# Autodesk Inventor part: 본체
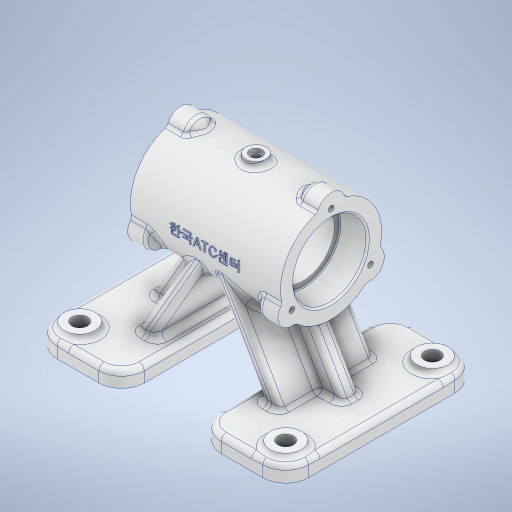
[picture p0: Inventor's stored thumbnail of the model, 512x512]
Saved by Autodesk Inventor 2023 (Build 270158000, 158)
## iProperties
Created: 2026-04
Part Number: 본체
Material: 알루미늄 6061
Document SubType Name: Modeling
Designer: 4강의실
Density: 2.7 g/cm^3
Appearance: 알루미늄 - 평지
Mass: 773.015 g
Surface Area: 685.715 cm^2
Volume: 286.302 cm^3
Author: 4강의실
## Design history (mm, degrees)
sketch "스케치1"
  geometry: L1 (-72, 55)-(72, 55); L2 (72, 55)-(72, -55); L3 (72, -55)-(-72, -55); L4 (-72, -55)-(-72, 55); L5 (-72, 55)-(72, -55); L6 (72, 55)-(-72, -55); L7 (-22, 55)-(22, 55); L8 (22, 55)-(22, -55); L9 (22, -55)-(-22, -55); L10 (-22, -55)-(-22, 55); L11 (-22, 55)-(22, -55); L12 (22, 55)-(-22, -55); 5 further points
  constraints: 24 end point, 4 midpoint, 4 parallel, 2 perpendicular, 1 collinear, 1 horizontal
  dimensions: "d0" = 144 distance of L1.start L1.end; "d1" = 110 distance of L1.end L2.end; "d2" = 44 distance of L7.start L7.end; "d3" = 110 distance of L9.end L7.start; "d116" = 50 distance from line of point (22, 55) L2; "d117" = 0 distance from line of point (22, 55) L1; "d118" = 50 distance from line of point (22, -55) L2; "d119" = 110 distance from line of point (22, -55) L1; "d120" = 94 distance from line of point (-22, 55) L2; "d121" = 0 distance from line of point (-22, 55) L1; "d122" = 94 distance from line of point (-22, -55) L2; "d123" = 110 distance from line of point (-22, -55) L1
extrude "돌출1" new body sketch "스케치1" distance "d4" = 9; taper "d5" = 0 deg
fillet "모깎기1" dims "d6" = 13
sketch "스케치2"
  geometry: L1 (59, -42)-(-59, -42); L2 (-59, -42)-(-59, 42); L3 (-59, 42)-(59, 42); L4 (59, 42)-(59, -42); L5 (59, -42)-(-59, 42); L6 (-59, -42)-(59, 42); C1 r 9 at (-59, 42); C2 r 9 at (-59, -42); C3 r 9 at (59, -42); C4 r 9 at (59, 42); 1 further point
  constraints: 12 end point, 4 centre point, 4 coincident, 2 midpoint, 2 parallel, 1 horizontal, 1 perpendicular
  dimensions: "d7" = 118 distance of L1.start L1.end; "d8" = 84 distance of L1.end L2.end; "d9" = 18 diameter of C1; "d10" = 18 diameter of C2; "d11" = 18 diameter of C3; "d12" = 18 diameter of C4
extrude "돌출2" join sketch "스케치2" distance "d13" = 3; taper "d14" = 0 deg
sketch "스케치3"
  geometry: C1 r 9 at (0, 0) reference; C2 r 9 at (118, 0) reference; C3 r 9 at (118, -84) reference; C4 r 9 at (0, -84) reference; 5 further points
  constraints: 4 coincident
hole "구멍1" sketch "스케치3" at (0, 0), (118, 0), (118, -84), (0, -84) diameter "d15" = 9; stored, may be unused: countersink angle "d19" = 90 deg, drill point angle "d21" = 118 deg; dims "d16" = 12, "d17" = 4, "d18" = 2, "d20" = 14
sketch "스케치4"
  geometry: L1 (0, 0)-(72, 0); C1 r 29 at (72, 0)
  constraints: 2 end point, 1 centre point, 1 coincident, 1 horizontal
  dimensions: "d22" = 72 distance of L1.start L1.end; "d23" = 58 diameter of C1
extrude "돌출3" join sketch "스케치4" stored distance "d24" = 86; taper "d25" = 0 deg
sketch "스케치5"
  geometry: C1 r 29 at (0, 0) reference; 2 further points
  constraints: 1 coincident
hole "구멍2" sketch "스케치5" at (0, 0) diameter "d26" = 36; stored, may be unused: countersink angle "d30" = 90 deg, drill point angle "d32" = 118 deg; dims "d27" = 6, "d28" = 42, "d29" = 16, "d31" = 8
sketch "스케치6"
  geometry: C1 r 18 at (0, 0) reference; C2 r 21 at (0, 0); 1 further point
  constraints: 1 centre point, 1 coincident
  dimensions: "d33" = 42 diameter of C2
extrude "돌출4" cut sketch "스케치6" distance "d34" = 16; taper "d35" = 0 deg
sketch "스케치7" dims "d36" = 52
  geometry: L1 (0, 0)-(0, 26); C1 r 21 at (0, 0) reference; C2 r 8 at (0, 26); 4 further points
  constraints: 2 coincident, 2 end point, 1 centre point, 1 vertical, 3 other
  dimensions: "d38" = 16 diameter of C2
extrude "돌출5" join sketch "스케치7" distance "d39" = 10; taper "d40" = 0 deg
sketch "스케치8"
  geometry: L1 (-33, 99.942)-(-33, 106) reference; L2 (-33, 106)-(-24.181, 97.181); L3 (-33, 101)-(43, 101) reference; L4 (-43, 43)-(43, 43) reference; L5 (27, 90)-(-27, 90) reference; L6 (0, 90)-(0, 112.184); L7 (-33, 106)-(-33, 97.181); L8 (-33, 97.181)-(-24.181, 97.181); L9 (-43, 51)-(-43, 93) reference; L10 (-43, 72)-(0, 72); L11 (-33, 106)-(-33, 98); L12 (-33, 98)-(-20.448, 98); 3 further points
  constraints: 14 end point, 2 midpoint, 2 perpendicular, 2 point on line, 1 horizontal, 1 vertical
  dimensions: "d41" = 45 deg angle of L6 L2; "d42" = 8 distance of L1.end L11.end; "d124" = 7.18091 distance between parallel lines of L5 L8; "d125" = 22.18414 distance from line of L6.end L5; "d126" = 33 distance from line of L10.end L1; "d127" = 12.55187 distance from line of L12.end L1; "d128" = 8 distance from line of point (-25, 98) L5; "d129" = 8 distance from line of point (-25, 98) L1; "d130" = 9.94231 distance from line of point (-33, 99.942) L5; "d131" = 0 distance from line of point (-33, 99.942) L1
revolve "회전1" sketch "스케치8" stored, may be unused: angle "d43" = 90 deg
sketch "스케치9"
  geometry: C1 r 18 at (0, 72) reference; C2 r 21 at (0, 72); 1 further point
  constraints: 1 centre point, 1 coincident
  dimensions: "d47" = 42 diameter of C2
extrude "돌출6" cut sketch "스케치9" distance "d48" = 16; taper "d49" = 0 deg
sketch "스케치10"
  geometry: C1 r 21 at (0, 72) reference; C2 r 21 at (0, 72); 1 further point
  constraints: 1 centre point, 1 coincident
  dimensions: "d50" = 42 diameter of C2
extrude "돌출7" cut sketch "스케치10" distance "d51" = 16; taper "d52" = 0 deg
sketch "스케치11" dims "d53" = 52
  geometry: L1 (0, 72)-(0, 98); C1 r 21 at (0, 72) reference; 3 further points
  constraints: 2 coincident, 2 end point, 1 vertical, 1 vertical alignment, 2 other
hole "구멍3" sketch "스케치11" at (0, 98) diameter "d54" = 3.242; stored, may be unused: countersink angle "d58" = 90 deg, drill point angle "d60" = 118 deg; dims "d55" = 8, "d56" = 42, "d57" = 16, "d59" = 10
sketch "스케치12"
  geometry: L1 (22, 0)-(22, 9) reference; L2 (22, 0)-(32, 0); L3 (35, 0)-(22, 0) reference; L4 (32, 0)-(32, 9); L5 (22, 9)-(35, 9) reference; L6 (32, 9)-(12.37, 43); L7 (-43, 43)-(43, 43) reference; L8 (0, 0)-(0, 43); L9 (19.298, 47)-(41.238, 9); L10 (40, -8)-(22, -8); L11 (35, 9)-(59, 9) reference; L12 (22, 9)-(35, 9) reference; L13 (-43, 43)-(43, 43) reference; L14 (0, 43)-(0, 64.426); L15 (0, 64.426)-(12.37, 43); L16 (0, 64.426)-(0, 80.426); L17 (0, 80.426)-(21.608, 43); 1 further point
  constraints: 20 end point, 8 point on line, 2 vertical, 1 collinear, 1 parallel, 1 perpendicular
  dimensions: "d64" = 10 distance of L1.start L2.end; "d65" = 30 deg angle of L8 L6; "d66" = 8 distance between parallel lines of L6 L9; "d132" = 17 distance between parallel lines of L10 L11; "d133" = 18 distance from line of L10.start L1; "d134" = 0 distance from line of L10.end L1; "d135" = 38 distance from line of L9.start L11; "d136" = 38 distance from line of point (19.298, 47) L11; "d137" = 2.70171 distance from line of point (19.298, 47) L1; "d138" = 34 distance from line of L8.end L11
extrude "돌출8" join sketch "스케치12" stored distance "d67" = 54; taper "d68" = 0 deg
sketch "스케치13"
  geometry: L1 (10.975, 61.417)-(41.238, 9) reference; L2 (35.464, 43)-(55.094, 9); L3 (59, 9)-(35, 9) reference; L4 (-43, 43)-(43, 43) reference; 1 further point
  constraints: 2 end point, 2 point on line, 1 parallel
  dimensions: "d69" = 12 distance between parallel lines of L1 L2
feature "리브1" sketch "스케치13" dims "d70" = 1, "d71" = 10, "d72" = 0, "d73" = 0, "d74" = 1, "d75" = 1
fillet "모깎기2" dims "d76" = 3
fillet "모깎기3" dims "d77" = 3
fillet "모깎기4" dims "d78" = 3
fillet "모깎기6" dims "d80" = 3
fillet "모깎기7" dims "d81" = 3
node "작업 평면1"
sketch "스케치17"
  geometry: C1 r 6 at (0, 0); 1 further point
  constraints: 1 centre point, 1 coincident
  dimensions: "d86" = 12 diameter of C1
extrude "돌출10" join sketch "스케치17" stored distance "d87" = 10; taper "d88" = 0 deg
sketch "스케치18"
  geometry: C1 r 3.5 at (0, 0); 1 further point
  constraints: 1 centre point, 1 coincident
  dimensions: "d89" = 7 diameter of C1
extrude "돌출11" cut sketch "스케치18" distance "d90" = 2; taper "d91" = 0 deg
sketch "스케치19"
  geometry: 2 further points
  constraints: 1 coincident
hole "구멍4" sketch "스케치19" at (0, 0) diameter "d92" = 5.1881; stored, may be unused: countersink angle "d96" = 90 deg, drill point angle "d98" = 118 deg; dims "d93" = 12, "d94" = 4, "d95" = 2, "d97" = 16
node "작업 평면2"
fillet "모깎기8" dims "d100" = 3
fillet "모깎기9" dims "d101" = 3
fillet "모깎기10" dims "d102" = 3
fillet "모깎기11" dims "d103" = 3
fillet "모깎기12" dims "d104" = 0.6
chamfer "모따기1" distance "d105" = 1; stored, may be unused: second distance "d106" = 2, angle "d107" = 45 deg
fillet "모깎기13" dims "d108" = 3
fillet "모깎기14" dims "d109" = 3
sketch "스케치21"
  geometry: 2 further points
  constraints: 1 vertical alignment, 1 other
  dimensions: "d110" = 72 distance of point (59, 72) point (59, 0)
feature "엠보싱1" sketch "스케치21" dims "d111" = 0.5, "d112" = 0
sketch "스케치22"
  geometry: C1 r 18 at (0, 72) reference; C2 r 18 at (0, 72); 1 further point
  constraints: 1 centre point, 1 coincident
  dimensions: "d113" = 36 diameter of C2
extrude "돌출12" cut sketch "스케치22" extent not by distance; stored distance "d114" = 2; taper "d115" = 0 deg
node "솔리드1"
pattern_circular "원형 패턴1" dims angle "d45" = 360 deg
mirror "미러1"
pattern_circular "원형 패턴2" dims angle "d62" = 360 deg
mirror "미러2"
mirror "미러3"
mirror "미러4"
mirror "미러5"
feature "A9D066F2-1C7D-4E18-AEED-F7BC21143FA4" dims "d15" = 9, "d16" = 12, "d17" = 4, "d18" = 2, "d19" = 90 deg, "d20" = 14, "d21" = 118 deg
other parameters: "d82" = -104, "d99" = -72
